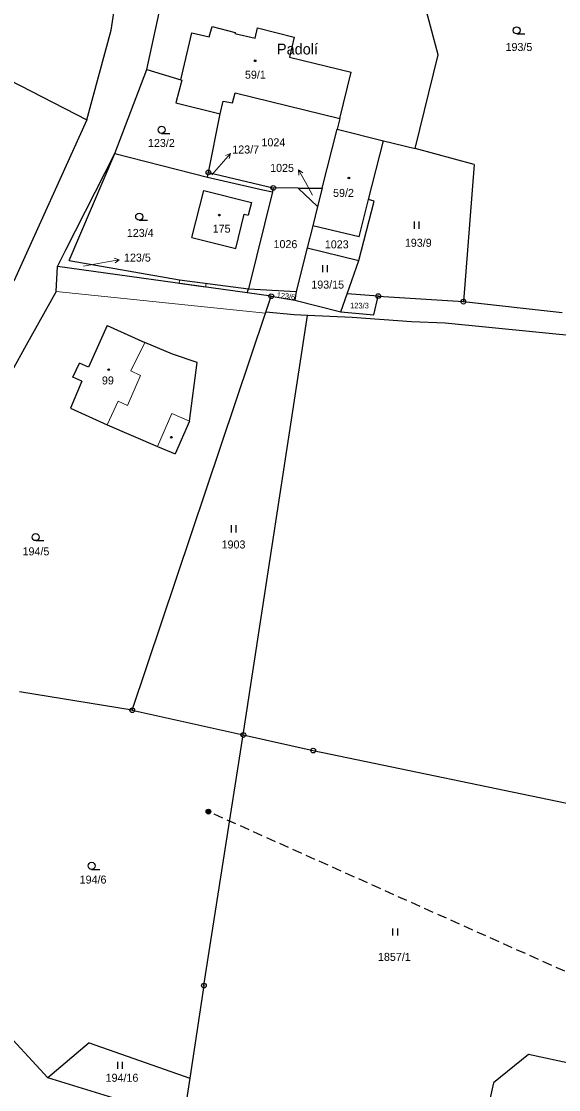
# Model space of a CAD drawing. Extents: x -601131 to -597152, y -1058536 to -1055911.
# Drawn here: x -599351.3 to -599237.3, y -1056861.6 to -1056634.8 of the extents above; entities that cross this region are included whole.
import ezdxf
from ezdxf.enums import TextEntityAlignment as Align

# ---------------------------------------------------------------- set-up
doc = ezdxf.new("R2010")
doc.units = 0
doc.header["$LTSCALE"] = 0.68
doc.linetypes.add('MEDIUM_DASHED', pattern=[4.5, 3, -1.5])
for name, color, linetype, lineweight in [('1', 7, 'Continuous', 25), ('13', 7, 'Continuous', 13), ('3', 7, 'Continuous', 25), ('4', 7, 'Continuous', 13), ('5', 7, 'Continuous', 25), ('6', 7, 'Continuous', 25), ('7', 7, 'Continuous', 13), ('8', 7, 'Continuous', 25)]:
    doc.layers.add(name, color=color, linetype=linetype, lineweight=lineweight)
doc.layers.add('2', color=7, linetype='Continuous')

msp = doc.modelspace()

# ---------------------------------------------------------------- linework, layer by layer
at = {"layer": '1'}
for p, q in [((-599332.25, -1056636.61), (-599328.38, -1056611.8)), ((-599262.81, -1056641.86), (-599267.88, -1056622.9)), ((-599324.69, -1056645.02), (-599320.84, -1056627.49)), ((-599311.47, -1056638.06), (-599310.83, -1056635.87)), ((-599310.83, -1056635.87), (-599305.94, -1056637.15)), ((-599301.69, -1056638.35), (-599301.17, -1056636.14)), ((-599301.17, -1056636.14), (-599293.41, -1056638.12)), ((-599337.39, -1056655.67), (-599332.25, -1056636.61)), ((-599317.46, -1056647.21), (-599315.11, -1056637.2)), ((-599315.11, -1056637.2), (-599311.47, -1056638.06)), ((-599305.94, -1056637.15), (-599305.99, -1056637.35)), ((-599305.99, -1056637.35), (-599301.69, -1056638.35)), ((-599293.41, -1056638.12), (-599294.39, -1056642.35)), ((-599364, -1056641.99), (-599337.39, -1056655.67)), ((-599294.39, -1056642.35), (-599281.28, -1056645.57)), ((-599267.7, -1056661.8), (-599262.81, -1056641.86)), ((-599331.45, -1056662.85), (-599324.69, -1056645.02)), ((-599324.69, -1056645.02), (-599317.46, -1056647.21)), ((-599317.25, -1056647.26), (-599318.49, -1056652.06)), ((-599317.46, -1056647.21), (-599317.25, -1056647.26)), ((-599283.73, -1056655.43), (-599281.28, -1056645.57)), ((-599306.46, -1056652.1), (-599305.91, -1056649.92)), ((-599305.91, -1056649.92), (-599283.73, -1056655.43)), ((-599318.49, -1056652.06), (-599309.12, -1056654.38)), ((-599309.12, -1056654.38), (-599308.46, -1056651.73)), ((-599308.46, -1056651.73), (-599306.46, -1056652.1)), ((-599311.6, -1056666.84), (-599309.12, -1056654.38)), ((-599337.39, -1056655.67), (-599352.88, -1056689.93)), ((-599283.73, -1056655.43), (-599284.3, -1056657.69)), ((-599287.45, -1056670.2), (-599284.3, -1056657.69)), ((-599284.3, -1056657.69), (-599274.46, -1056660.11)), ((-599341.85, -1056683.28), (-599331.45, -1056662.85)), ((-599341.18, -1056685.58), (-599331.45, -1056662.85)), ((-599331.45, -1056662.85), (-599311.78, -1056667.86)), ((-599255.16, -1056665.2), (-599267.7, -1056661.8)), ((-599255.16, -1056665.2), (-599257.46, -1056694.29)), ((-599311.78, -1056667.86), (-599311.6, -1056666.84)), ((-599311.78, -1056667.86), (-599300.02, -1056670.54)), ((-599311.6, -1056666.84), (-599297.82, -1056670.13)), ((-599297.82, -1056670.13), (-599298, -1056671)), ((-599292.56, -1056670.16), (-599297.82, -1056670.13)), ((-599292.56, -1056670.16), (-599287.45, -1056670.2)), ((-599292.56, -1056670.16), (-599288.43, -1056674.08)), ((-599287.45, -1056670.2), (-599288.43, -1056674.08)), ((-599315.11, -1056680.7), (-599312.55, -1056670.68)), ((-599312.55, -1056670.68), (-599302.46, -1056673.25)), ((-599298, -1056671), (-599303.12, -1056691.55)), ((-599300.02, -1056670.54), (-599298, -1056671)), ((-599279.58, -1056680.54), (-599277.59, -1056672.59)), ((-599276.44, -1056672.95), (-599277.59, -1056672.59)), ((-599302.46, -1056673.25), (-599303.14, -1056675.93)), ((-599288.43, -1056674.08), (-599289.47, -1056678.21)), ((-599279.66, -1056685.52), (-599276.44, -1056672.95)), ((-599305.8, -1056683), (-599304, -1056675.72)), ((-599304, -1056675.72), (-599303.14, -1056675.93)), ((-599279.58, -1056680.54), (-599289.47, -1056678.21)), ((-599315.11, -1056680.7), (-599305.8, -1056683)), ((-599343.65, -1056686.81), (-599341.85, -1056683.28)), ((-599290.66, -1056682.84), (-599279.66, -1056685.52)), ((-599341.18, -1056685.58), (-599317.75, -1056689.69)), ((-599282.18, -1056692.66), (-599279.66, -1056685.52)), ((-599343.93, -1056692.1), (-599343.65, -1056686.81)), ((-599303.34, -1056692.43), (-599343.65, -1056686.81)), ((-599317.75, -1056689.69), (-599303.12, -1056691.55)), ((-599343.93, -1056692.1), (-599350.26, -1056703.54)), ((-599303.34, -1056692.43), (-599303.12, -1056691.55)), ((-599298.27, -1056693.14), (-599303.34, -1056692.43)), ((-599303.12, -1056691.55), (-599292.94, -1056692.11)), ((-599292.94, -1056692.11), (-599293.24, -1056693.99)), ((-599283.51, -1056696.42), (-599282.18, -1056692.66)), ((-599275.55, -1056693.1), (-599282.18, -1056692.66)), ((-599299.41, -1056696.54), (-599298.27, -1056693.14)), ((-599298.27, -1056693.14), (-599293.24, -1056693.99)), ((-599293.24, -1056693.99), (-599283.51, -1056696.42)), ((-599276.52, -1056697.09), (-599275.55, -1056693.1)), ((-599275.55, -1056693.1), (-599257.46, -1056694.29)), ((-599257.46, -1056694.29), (-599236.54, -1056696.59)), ((-599327.76, -1056781.06), (-599299.47, -1056696.73)), ((-599304.19, -1056786.31), (-599290.57, -1056697.24)), ((-599299.47, -1056696.73), (-599299.41, -1056696.54)), ((-599293.37, -1056697.12), (-599299.41, -1056696.54)), ((-599290.57, -1056697.24), (-599293.37, -1056697.12)), ((-599281.07, -1056697.66), (-599290.57, -1056697.24)), ((-599283.51, -1056696.42), (-599276.52, -1056697.09)), ((-599333.09, -1056699.36), (-599337.08, -1056708.18)), ((-599333.09, -1056699.36), (-599325.13, -1056702.94)), ((-599268.48, -1056698.56), (-599281.07, -1056697.66)), ((-599261.35, -1056698.89), (-599268.48, -1056698.56)), ((-599229.72, -1056702.02), (-599261.35, -1056698.89)), ((-599350.26, -1056703.54), (-599361.8, -1056724.28)), ((-599319.24, -1056705.45), (-599325.13, -1056702.94)), ((-599313.98, -1056707.24), (-599319.24, -1056705.45)), ((-599340.35, -1056710.34), (-599338.97, -1056707.33)), ((-599337.08, -1056708.18), (-599338.97, -1056707.33)), ((-599315.63, -1056719.66), (-599313.98, -1056707.24)), ((-599338.44, -1056711.16), (-599340.89, -1056716.88)), ((-599338.44, -1056711.16), (-599340.35, -1056710.34)), ((-599340.89, -1056716.88), (-599333.11, -1056720.45)), ((-599315.63, -1056719.66), (-599318.68, -1056726.63)), ((-599333.11, -1056720.45), (-599322.4, -1056725.02)), ((-599322.4, -1056725.02), (-599318.68, -1056726.63)), ((-599327.76, -1056781.06), (-599351.73, -1056777.15)), ((-599327.76, -1056781.06), (-599304.19, -1056786.31)), ((-599312.55, -1056839.53), (-599304.19, -1056786.31)), ((-599304.19, -1056786.31), (-599289.36, -1056789.62)), ((-599289.36, -1056789.62), (-599186.88, -1056810.87)), ((-599345.66, -1056859.14), (-599360.82, -1056842.71)), ((-599336.89, -1056851.67), (-599345.66, -1056859.14)), ((-599336.89, -1056851.67), (-599315.57, -1056859.19)), ((-599243.65, -1056854.14), (-599251.08, -1056860.19)), ((-599233.79, -1056856.28), (-599243.65, -1056854.14)), ((-599316.91, -1056867.93), (-599345.66, -1056859.14)), ((-599251.08, -1056860.19), (-599252.44, -1056866.27))]:
    msp.add_line(p, q, dxfattribs=at)
for points in [[(-599277.59, -1056672.59), (-599274.46, -1056660.11), (-599267.7, -1056661.8)], [(-599289.47, -1056678.21), (-599290.66, -1056682.84), (-599292.94, -1056692.11)], [(-599312.55, -1056839.53), (-599315.57, -1056859.19), (-599316.91, -1056867.93)]]:
    msp.add_lwpolyline(points, dxfattribs=at)
at = {"layer": '13'}
msp.add_lwpolyline([(-599317.84, -1056690.41), (-599312.2, -1056691.2), (-599312.1, -1056690.41), (-599317.75, -1056689.69)], close=True, dxfattribs=at)
at = {"layer": '3'}
for p, q in [((-599246.153, -1056637.43), (-599244.403, -1056637.43)), ((-599321.533, -1056658.55), (-599319.783, -1056658.55)), ((-599326.283, -1056676.99), (-599324.533, -1056676.99)), ((-599267.861, -1056678.8), (-599267.861, -1056677.3)), ((-599266.86, -1056678.8), (-599266.86, -1056677.3)), ((-599287.321, -1056688.01), (-599287.321, -1056686.51)), ((-599286.32, -1056688.01), (-599286.32, -1056686.51)), ((-599306.681, -1056743.28), (-599306.681, -1056741.78)), ((-599305.68, -1056743.28), (-599305.68, -1056741.78)), ((-599348.263, -1056745.04), (-599346.513, -1056745.04)), ((-599336.383, -1056814.85), (-599334.633, -1056814.85)), ((-599272.421, -1056828.88), (-599272.421, -1056827.38)), ((-599271.42, -1056828.88), (-599271.42, -1056827.38)), ((-599330.861, -1056857.23), (-599330.861, -1056855.73)), ((-599329.86, -1056857.23), (-599329.86, -1056855.73))]:
    msp.add_line(p, q, dxfattribs=at)
for centre in [(-599246.1529, -1056636.6798), (-599321.5329, -1056657.7998), (-599326.2829, -1056676.2398), (-599348.2629, -1056744.2898), (-599336.3829, -1056814.0998)]:
    msp.add_circle(centre, 0.75, dxfattribs=at)
at = {"layer": '4'}
for p, q in [((-599343.93, -1056692.1), (-599299.47, -1056696.73)), ((-599328.04, -1056709), (-599325.13, -1056702.94)), ((-599328.8, -1056716.36), (-599326.03, -1056709.97)), ((-599328.04, -1056709), (-599326.03, -1056709.97)), ((-599330.76, -1056715.44), (-599333.11, -1056720.45)), ((-599330.76, -1056715.44), (-599328.8, -1056716.36)), ((-599322.4, -1056725.02), (-599319.37, -1056718.03)), ((-599319.37, -1056718.03), (-599315.63, -1056719.66))]:
    msp.add_line(p, q, dxfattribs=at)
at = {"layer": '5'}
for centre in [(-599301.6768, -1056643.1392), (-599281.7868, -1056668.0192), (-599309.2868, -1056675.9192), (-599332.7668, -1056708.7292), (-599319.4768, -1056723.0792)]:
    msp.add_circle(centre, 0.175, dxfattribs=at)
at = {"layer": '6', "linetype": 'MEDIUM_DASHED'}
msp.add_line((-599168.92, -1056866.53), (-599311.59, -1056802.59), dxfattribs=at)
at = {"layer": '6'}
for radius in [0.5, 0.4, 0.3, 0.2, 0.1]:
    msp.add_circle((-599311.5934, -1056802.5899), radius, dxfattribs=at)
at = {"layer": '7'}
for p, q in [((-599306.911, -1056662.815), (-599307.946, -1056663.242)), ((-599292.455, -1056666.315), (-599292.407, -1056667.434)), ((-599330.515, -1056685.389), (-599331.588, -1056685.07))]:
    msp.add_line(p, q, dxfattribs=at)
for points in [[(-599310.89, -1056667.36), (-599308.88, -1056665.08), (-599306.911, -1056662.815), (-599307.19, -1056663.899)], [(-599289.49, -1056671.69), (-599291, -1056668.94), (-599292.455, -1056666.315), (-599291.531, -1056666.948)], [(-599338.15, -1056686.77), (-599333.47, -1056685.91), (-599330.515, -1056685.389), (-599331.414, -1056686.056)]]:
    msp.add_lwpolyline(points, dxfattribs=at)
at = {"layer": '8'}
for centre, radius in [((-599311.6, -1056666.8399), 0.5), ((-599311.6, -1056666.8399), 0.0303), ((-599297.82, -1056670.1299), 0.5), ((-599297.82, -1056670.1299), 0.0303), ((-599298.27, -1056693.1399), 0.5), ((-599275.55, -1056693.0999), 0.5), ((-599275.55, -1056693.0999), 0.0303), ((-599298.27, -1056693.1399), 0.0303), ((-599257.46, -1056694.2899), 0.5), ((-599257.46, -1056694.2899), 0.0303), ((-599327.76, -1056781.0599), 0.5), ((-599327.76, -1056781.0599), 0.0303), ((-599304.19, -1056786.3099), 0.5), ((-599304.19, -1056786.3099), 0.0303), ((-599289.36, -1056789.6199), 0.5), ((-599289.36, -1056789.6199), 0.0303), ((-599312.55, -1056839.5299), 0.5), ((-599312.55, -1056839.5299), 0.0303)]:
    msp.add_circle(centre, radius, dxfattribs=at)

# ---------------------------------------------------------------- texts
at = {"layer": '2'}
for s, height, p in [('193/5', 1.7, (-599248.53, -1056641.064)), ('59/1', 1.7, (-599303.84, -1056646.945)), ('123/2', 1.7, (-599324.43, -1056661.445)), ('123/7', 1.7, (-599306.53, -1056662.834)), ('59/2', 1.7, (-599285.14, -1056672.045)), ('123/4', 1.7, (-599328.92, -1056680.545)), ('175', 1.7, (-599310.69, -1056679.635)), ('193/9', 1.7, (-599269.9, -1056682.635)), ('123/5', 1.7, (-599329.52, -1056685.785)), ('193/15', 1.7, (-599289.76, -1056691.515)), ('123/3', 1.19, (-599281.53, -1056695.727)), ('99', 1.7, (-599334.2, -1056711.865)), ('194/5', 1.7, (-599351.05, -1056748.165)), ('194/6', 1.7, (-599338.93, -1056817.865)), ('194/16', 1.7, (-599333.42, -1056859.945))]:
    msp.add_text(s, height=height, dxfattribs=at).set_placement(p)
for s, p in [('1024', (-599297.81, -1056661.304)), ('1026', (-599295.25, -1056682.925)), ('1023', (-599284.36, -1056682.965)), ('1903', (-599306.27, -1056746.702)), ('1857/1', (-599272.13, -1056834.275))]:
    msp.add_text(s, height=1.7, dxfattribs=at).set_placement(p, align=Align.CENTER)
msp.add_text('1025', height=1.7, dxfattribs=at).set_placement((-599293.44, -1056666.735), align=Align.RIGHT)
msp.add_text('123/6', height=1.14, rotation=353, dxfattribs=at).set_placement((-599297.154, -1056693.412))
at = {"layer": '7'}
msp.add_text('Padolí', height=2.3, dxfattribs=at).set_placement((-599292.69, -1056641.805), align=Align.CENTER)

doc.saveas('drawing.dxf')
